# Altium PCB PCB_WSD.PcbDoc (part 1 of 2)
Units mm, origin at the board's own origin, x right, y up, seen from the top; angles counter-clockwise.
Board outline 55.63 x 89.28 mm, 2 copper layers (Top Layer, Bottom Layer); 49 components, 56 nets, 208 pads, 22 vias.
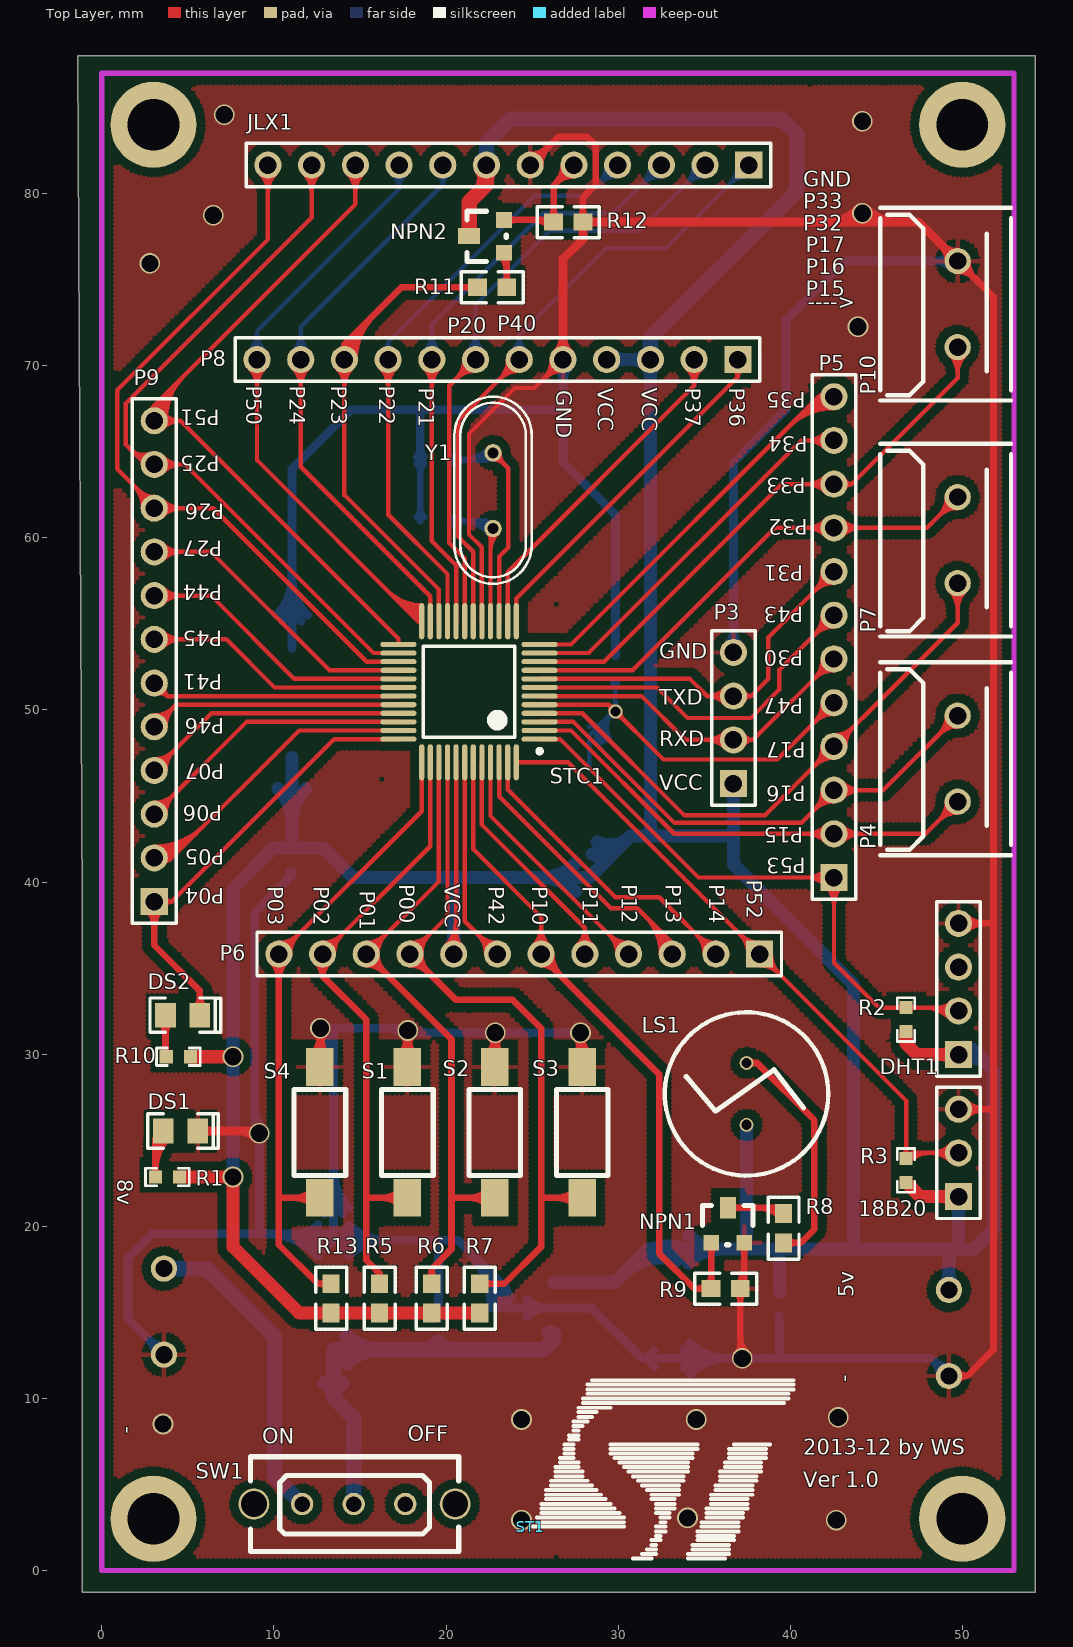
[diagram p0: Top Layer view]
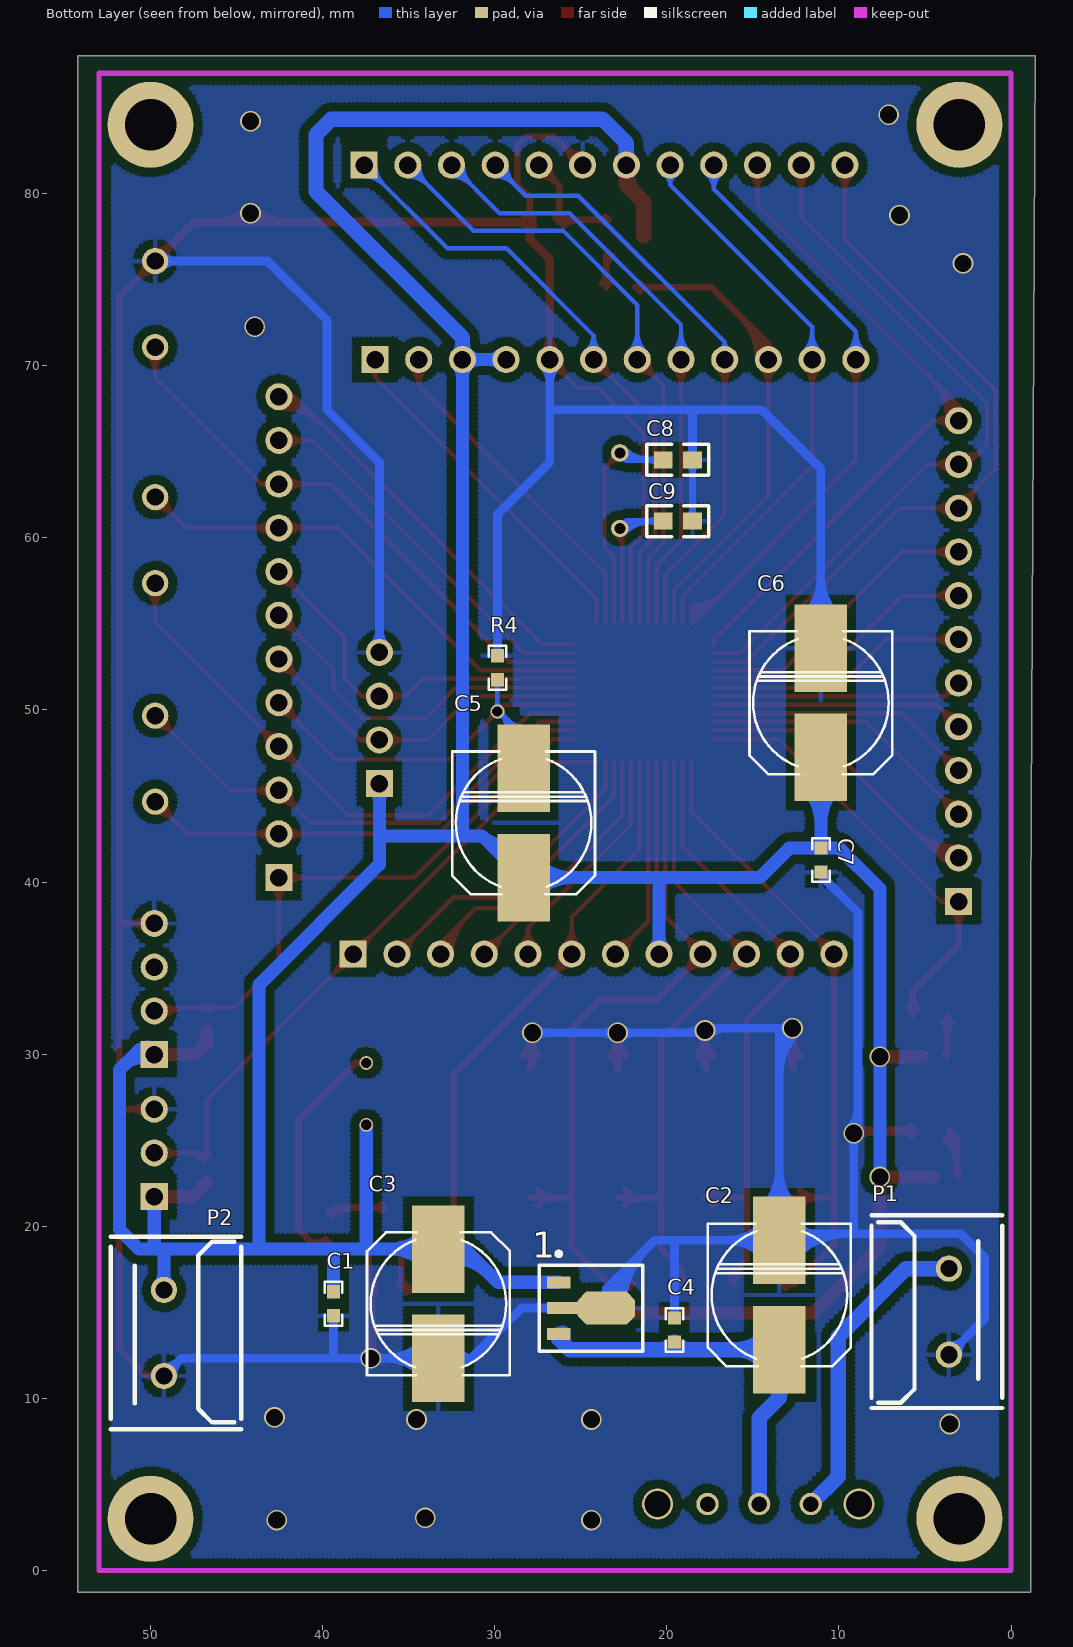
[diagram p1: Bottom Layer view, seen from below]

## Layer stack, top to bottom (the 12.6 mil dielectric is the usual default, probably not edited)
Top Layer: signal copper 0.0356
Dielectric: dielectric 0.32, FR-4, Dk 4.8
Bottom Layer: signal copper 0.0356

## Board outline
-1.397,88.011 54.229,88.011 54.229,-1.27 -1.143,-1.27 -1.143,38.608

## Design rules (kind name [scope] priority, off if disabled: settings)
Clearance Clearance_1 [All vs (INPolygon)] p1: gap=0.508
Clearance [All] p2: gap=0.2
ComponentClearance [All] p1: gap=0.254 collisioncheckmode=2
HoleSize [All] p1: absolutevalues=TRUE maxlimit=5 minlimit=0.025 maxpercent=80.000 minpercent=20.000
PolygonConnect [All] p1: connectstyle=Relief reliefconductorwidth=0.254 reliefentries=4 polygonreliefangle="90 Angle"
RoutingVias [All] p1: holewidth=0.5 width=0.8 viastyle="Through Hole" minholewidth=0.5 minwidth=0.8 maxholewidth=1.2 maxwidth=1.8
SolderMaskExpansion [All] p1: expansion=0.102
TestPointUsage [All] p1: valid=0 allowmultiple=FALSE
Testpoint [All] p1: side=15 testpointundercomponent=TRUE minsize=1.016 maxsize=2.54 preferedsize=1.524 minholesize=0 maxholesize=1.016 preferedholesize=0.813 testpointgrid=0.025 style=1023 order=1234567890
Width [All] p1: maxlimit=1.016 minlimit=0.2 preferedwidth=0.254 toplayer_prefwidth=0.381 bottomlayer_prefwidth=0.508 minimp=50.000000 maximp=50.000000 favimp=50.000000
16 further rules are at their usual default settings.

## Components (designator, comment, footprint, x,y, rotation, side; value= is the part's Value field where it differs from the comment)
1 "78L05-SOT89" SOT89 24.892,15.24 r270 bottom
18B20 "DS18B20" HDR1X3 49.784,21.717 r90 top (schematic designator 2)
C1 "Cap" 0603 39.37,15.494 r90 bottom
C2 "10uf" C310M 13.462,16.002 r270 bottom
C3 "10uf" C310M 33.274,15.494 r90 bottom
C4 "Cap" 0603 19.558,13.97 r270 bottom
C5 "10uf" C310M 28.321,43.434 r270 bottom
C6 "10uf" C310M 11.049,50.419 r270 bottom
C7 "104" 0603 11.049,41.275 r90 bottom
C8 "20pF" P0603 21.209,63.627 r180 bottom
C9 "20pF" P0603 21.209,60.071 r180 bottom
DHT1 "DHT11" HDR1X4 49.784,29.972 r90 top
DS1 "LED0" LED2012 4.572,25.527 r0 top
DS2 "LED0" LED2012 4.699,32.258 r0 top
JLX1 "JLX12864G-086-PC" HDR1X12 37.592,81.661 r180 top
LS1 "Bell" BEEP 37.465,27.686 r90 top
NPN1 "NPN8050" SOT23-T 34.925,18.542 r0 top
NPN2 "NPN8050" SOT23-T 23.876,76.073 r90 top
P1 "MHDR1X2" KF301-2P 0.508,10.033 r90 bottom
P2 "MHDR1X2" KF301-2P 52.324,18.796 r270 bottom
P3 "Header 4" HDR1X4 36.703,45.72 r90 top
P4 "MHDR1X2" KF301-2P 52.832,42.164 r90 top
P5 "Header 12" HDR1X12 42.545,40.259 r90 top
P6 "Header 12" HDR1X12 38.227,35.814 r180 top
P7 "MHDR1X2" KF301-2P 52.832,54.864 r90 top
P8 "Header 12" HDR1X12 36.957,70.358 r180 top
P9 "Header 12" HDR1X12 3.048,38.862 r90 top
P10 "MHDR1X2" KF301-2P 52.832,68.58 r90 top
R1 "Res2" 0603 3.81,22.86 r0 top
R2 "Res2" 0603 46.736,32.004 r270 top
R3 "Res2" 0603 46.736,23.241 r270 top
R4 "10K" 0603 29.845,52.451 r270 bottom
R5 "Res2" P0603 15.24,17.653 r270 top
R6 "Res2" P0603 20.066,13.953 r90 top
R7 "Res2" P0603 22.86,13.953 r90 top
R8 "1K" P0603 40.513,18.034 r90 top
R9 "1K" P0603 38.1,17.272 r180 top
R10 "Res2" 0603 4.445,29.845 r0 top
R11 "10K" P0603 20.828,73.66 r0 top
R12 "1K" P0603 28.956,79.248 r180 top
R13 "Res2" P0603 14.224,13.953 r90 top
S1 "SW-PB" KEY-SMD 16.256,28.448 r270 top
S2 "SW-PB" KEY-SMD 21.336,28.448 r270 top
S3 "SW-PB" KEY-SMD 26.416,28.448 r270 top
S4 "SW-PB" KEY-SMD 11.176,28.448 r270 top
ST1 "ST-WS" ST2 24.892,2.54 r0 top
STC1 "STC12C5A60S2" LQFP48_M 21.336,51.054 r180 top
SW1 "SW-SS12D07" SS-12F44 8.636,6.604 r270 top
Y1 "8MHz" XTA 22.733,62.738 r90 top

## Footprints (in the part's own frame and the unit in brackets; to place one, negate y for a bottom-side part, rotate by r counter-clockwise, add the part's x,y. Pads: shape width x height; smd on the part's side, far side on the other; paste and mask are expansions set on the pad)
0603 [mil]
  rect 30x30 smd: 1(-27.5,0) 2(27.5,0)
  silkscreen extent -50,-20 50,20
BEEP [mm]
  round 0.8 hole 0.6: 1(-1.8,0) 2(1.8,0)
  silkscreen extent -4.75,-4.75 4.75,4.75
C310M [mil]
  rect 200x120 smd: 1(125,0) 2(-125,0)
  silkscreen extent -163,-163 163,163
HDR1X3 [mil] "Connector; Header; 3 Position"
  rect 62x62 hole 40: 1(0,0)
  round 62 hole 40: 2(100,0) 3(200,0)
  silkscreen extent -50,-50 250,50
HDR1X4 [mil] "Connector; Header; 4 Position"
  rect 62x62 hole 40: 1(0,0)
  round 62 hole 40: 2(100,0) 3(200,0) 4(300,0)
  silkscreen extent -50,-50 350,50
HDR1X12 [mil] "Connector; Header; 12 Position"
  rect 62x62 hole 40: 1(0,0)
  round 62 hole 40: 2(100,0) 3(200,0) 4(300,0) 5(400,0) 6(500,0) 7(600,0) 8(700,0) 9(800,0) 10(900,0) 11(1000,0) 12(1100,0)
  silkscreen extent -50,-50 1150,50
KEY-SMD [mm]
  rect 2.2x1.6 smd: 1(-0.8,1.5) 2(6.8,1.5)
  silkscreen extent 0.5,0 5.5,3
KF301-2P [mm]
  round 1.524 hole 1: 1(2.5,3.1) 2(7.5,3.1)
  silkscreen extent -0.6,0 10.6,7.6
LED2012 [mm] "SMD LED 2mm x 1.2 mm"
  rect 1.2x1.45 smd: 1(-1,0) 2(1,0)
  silkscreen extent -1.9,-1 2.2,1
LQFP48_M [mm]
  oval 2.1x0.3 smd: 1(-4.1,2.75) 2(-4.1,2.25) 3(-4.1,1.75) 4(-4.1,1.25) 5(-4.1,0.75) 6(-4.1,0.25) 7(-4.1,-0.25) 8(-4.1,-0.75) 9(-4.1,-1.25) 10(-4.1,-1.75) 11(-4.1,-2.25) 12(-4.1,-2.75) 25(4.1,-2.75) 26(4.1,-2.25) 27(4.1,-1.75) 28(4.1,-1.25) 29(4.1,-0.75) 30(4.1,-0.25) 31(4.1,0.25) 32(4.1,0.75) 33(4.1,1.25) 34(4.1,1.75) 35(4.1,2.25) 36(4.1,2.75)
  oval 0.3x2.1 smd: 13(-2.75,-4.1) 14(-2.25,-4.1) 15(-1.75,-4.1) 16(-1.25,-4.1) 17(-0.75,-4.1) 18(-0.25,-4.1) 19(0.25,-4.1) 20(0.75,-4.1) 21(1.25,-4.1) 22(1.75,-4.1) 23(2.25,-4.1) 24(2.75,-4.1) 37(2.75,4.1) 38(2.25,4.1) 39(1.75,4.1) 40(1.25,4.1) 41(0.75,4.1) 42(0.25,4.1) 43(-0.25,4.1) 44(-0.75,4.1) 45(-1.25,4.1) 46(-1.75,4.1) 47(-2.25,4.1) 48(-2.75,4.1)
  silkscreen extent -4.23,-2.65 2.65,3.57
P0603 [mm]
  rect 1.1x1 smd: 1(1,0.9) 2(2.7,0.9)
  silkscreen extent 0.05,0 3.65,1.8
SOT23-T [mil]
  rect 36x36 smd: 1(19.49,19.69) 2(94.49,19.69)
  rect 36x50 smd: 3(57.49,99.69)
  silkscreen extent -1,15 114,105
SOT89 [mm] "SOT-89; Body 4.6 x 4.25 mm, inc. leads (LxW max)"
  oct 1.9x3.3 smd: 0(0,1.388)
  rect 0.7x1.35 smd: 1(-1.5,-1.388) 3(1.5,-1.388)
  rect 0.7x1.8 smd: 2(0,-1.162)
  silkscreen extent -3.27,-2.51 2.5,3.49
SS-12F44 [mm]
  round 1.8 hole 1.5: 0(2.75,11.9) 0(2.75,0.2)
  round 1.3 hole 0.9: 1(2.75,3) 2(2.75,6) 3(2.75,9)
  silkscreen extent 0,0 5.5,12.1
ST2 [mm]
  silkscreen extent 0.13,-1.85 15.3,8.51
XTA [mil]
  round 40 hole 25: 1(86.61,0) 2(-86.61,0)
  silkscreen extent -213,-89 215,89

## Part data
C1 C4: "Capacitor"
C2 C3 C5 C6: library part "Cap Pol3", "Polarized Capacitor (Surface Mount)"
C7 C8 C9: library part Cap, "Capacitor"
DS1 DS2: "Typical INFRARED GaAs LED"
LS1: "Electrical Bell"
P1 P2 P4 P7 P10: "Header, 2-Pin"
P3: "Header, 4-Pin"
P5 P6 P8 P9: "Header, 12-Pin"
R1 R2 R3 R5 R6 R7 R10 R13: "Resistor"
R4 R8 R9 R11 R12: library part Res2, "Resistor"
S1 S2 S3 S4: "Switch"
Y1: library part XTAL, "Crystal Oscillator"

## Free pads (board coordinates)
  round 5 hole 3: 0(3,3) 0(3,84) 0(50,3) 0(50,84)

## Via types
v1: diameter 1.2, hole 1, Top Layer to Bottom Layer, 21 vias
v2: diameter 0.8, hole 0.6, Top Layer to Bottom Layer, 1 vias

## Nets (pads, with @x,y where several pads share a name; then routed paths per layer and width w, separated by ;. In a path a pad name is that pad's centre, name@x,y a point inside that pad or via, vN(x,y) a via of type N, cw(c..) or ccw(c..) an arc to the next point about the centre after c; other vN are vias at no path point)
5V: 1.1 18B20.1 C1.2 C3.1 C5.1 C6.1 C7.2 DHT1.1 JLX1.7 LS1.1 NPN2.3 P2.1 P3.1 P6.8 P8.3 P8.4 R1.2 R2.2 R3.2 R5.2 R6.1 R7.1 R10.2 R13.1 STC1.41 | length 362.6
  Top Layer w0.254: P6.8@20.447,35.814 20.586,35.953 STC1.41@20.586,46.954 ; P6.8@19.98,36.281 ccw(c18.517,37.744) 20.586,37.744 cw(c18.517,37.744) P6.8@19.98,36.281 ; P6.8@20.16,36.101 ccw(c19.13,37.131) 20.586,37.131 cw(c19.13,37.131) P6.8@20.16,36.101 ; 20.586,37.073 ccw(c21.706,37.073) 20.914,36.281 cw(c21.706,37.073) 20.586,37.073
  Top Layer w0.762: R1.2@4.508,22.86 v1(7.62,22.86) 7.62,18.796 11.463,14.953 R13.1@13.324,14.953 R6.1@19.166,14.953 R7.1@21.96,14.953 ; R10.2@5.143,29.845 v1(7.62,29.845) ; R3.2@46.736,22.543 47.561,21.717 18B20.1@49.784,21.717 ; DHT1.1@49.784,29.972 47.371,29.972 46.736,30.607 R2.2@46.736,31.305 ; R2.2@46.736,31.305 ccw(c47.774,31.073) 47.022,30.321 cw(c47.774,31.073) R2.2@46.736,31.305 ; 48.803,21.717 cw(c48.803,20.736) 49.497,21.43 ccw(c48.803,20.736) 48.803,21.717 ; 48.803,21.717 ccw(c48.803,22.698) 49.497,22.004 cw(c48.803,22.698) 48.803,21.717 ; 48.803,29.972 cw(c48.803,28.991) 49.497,29.685 ccw(c48.803,28.991) 48.803,29.972 ; 48.803,29.972 ccw(c48.803,30.953) 49.497,30.259 cw(c48.803,30.953) 48.803,29.972
  Top Layer w0.889: NPN2.3@21.344,77.533 21.344,79.51 22.352,80.518 JLX1.7@22.352,81.661 ; 22.352,80.833 cw(c23.18,80.833) 22.594,81.419 ccw(c23.18,80.833) 22.352,80.833 ; 22.352,80.833 ccw(c21.524,80.833) 22.11,81.419 cw(c21.524,80.833) 22.352,80.833 ; 21.916,80.082 ccw(c21.127,80.87) 22.064,81.475 cw(c21.127,80.87) 21.916,80.082
  Bottom Layer w0.762: v1(7.62,22.86) 7.62,39.624 9.97,41.974 12.89,41.974 14.605,40.259 C5.1@28.321,40.259 30.734,42.672 ; C7.2@11.049,41.974 C6.1@11.049,47.244 ; P6.8@20.447,35.814 20.447,40.259 ; 1.1@26.28,16.74 29.821,16.74 31.75,18.669 50.673,18.669 51.816,19.812 51.816,29.083 50.927,29.972 DHT1.1@49.784,29.972 ; P8.4@29.337,70.358 P8.3@31.877,70.358 31.877,42.672 ; 36.703,42.672 30.734,42.672 ; P3.1@36.703,45.72 36.703,41.021 43.688,34.036 43.688,18.669 ; 37.465,18.669 LS1.1@37.465,25.886 ; C1.2@39.37,16.192 39.37,18.669 ; P2.1@49.121,16.192 P2.1@49.224,16.296 49.224,18.594 49.149,18.669 ; 49.784,18.669 18B20.1@49.784,21.717 ; 11.049,43.469 cw(c13.808,43.469) 11.857,45.42 ccw(c13.808,43.469) 11.049,43.469 ; 11.049,43.469 ccw(c8.29,43.469) 10.241,45.42 cw(c8.29,43.469) 11.049,43.469 ; 20.447,36.795 cw(c19.466,36.795) 20.16,36.101 ccw(c19.466,36.795) 20.447,36.795 ; 20.447,36.795 ccw(c21.428,36.795) 20.734,36.101 cw(c21.428,36.795) 20.447,36.795 ; 25.562,40.259 cw(c25.562,37.5) 27.513,39.451 ccw(c25.562,37.5) 25.562,40.259 ; 25.562,40.259 ccw(c25.562,43.018) 27.513,41.067 cw(c25.562,43.018) 25.562,40.259 ; 30.318,70.358 cw(c30.318,71.339) 29.624,70.645 ccw(c30.318,71.339) 30.318,70.358 ; 30.318,70.358 ccw(c30.318,69.377) 29.624,70.071 cw(c30.318,69.377) 30.318,70.358 ; 30.734,42.672 cw(c29.506,43.9) 28.791,42.317 ccw(c29.506,43.9) 30.734,42.672 ; 30.896,70.358 cw(c30.896,69.377) P8.3@31.59,70.071 ; 30.896,70.358 ccw(c30.896,71.339) 31.59,70.645 cw(c30.896,71.339) 30.896,70.358 ; 30.896,70.358 cw(c30.896,69.377) P8.3@31.59,70.071 ; P8.3@31.59,70.071 cw(c30.896,69.377) 31.877,69.377 ; P8.3@31.59,70.071 cw(c30.896,69.377) 31.877,69.377 ; 31.877,69.377 cw(c32.858,69.377) 32.164,70.071 ccw(c32.858,69.377) 31.877,69.377 ; 36.033,18.669 cw(c36.033,21.428) 34.082,19.477 ccw(c36.033,21.428) 36.033,18.669 ; 36.033,18.669 ccw(c36.033,15.91) 34.082,17.861 cw(c36.033,15.91) 36.033,18.669 ; 36.703,44.739 cw(c37.684,44.739) 36.99,45.433 ccw(c37.684,44.739) 36.703,44.739 ; 36.703,44.739 ccw(c35.722,44.739) 36.416,45.433 cw(c35.722,44.739) 36.703,44.739 ; 49.224,17.216 cw(c48.304,17.216) 48.955,16.565 ccw(c48.304,17.216) 49.224,17.216 ; 49.224,17.216 ccw(c50.144,17.216) 49.493,16.565 cw(c50.144,17.216) 49.224,17.216 ; 49.784,20.736 cw(c50.765,20.736) 50.071,21.43 ccw(c50.765,20.736) 49.784,20.736 ; 49.784,20.736 ccw(c48.803,20.736) 49.497,21.43 cw(c48.803,20.736) 49.784,20.736 ; 50.765,29.972 cw(c50.765,30.953) 50.071,30.259 ccw(c50.765,30.953) 50.765,29.972 ; 50.765,29.972 ccw(c50.765,28.991) 50.071,29.685 cw(c50.765,28.991) 50.765,29.972 ; C5.1@28.478,41.622 ccw(c29.021,42.826) 29.954,41.892 cw(c29.021,42.826) C5.1@28.478,41.622 ; 30.342,17.261 cw(c32.492,15.11) 33.386,18.017 ccw(c32.492,15.11) 30.342,17.261 ; 31.237,18.156 cw(c32.913,16.479) 33.61,18.746 ccw(c32.913,16.479) 31.237,18.156 ; DHT1.1@49.612,30.283 cw(c50.087,29.423) 50.781,30.118 ccw(c50.087,29.423) DHT1.1@49.612,30.283 ; DHT1.1@49.779,30.328 cw(c49.806,28.479) 51.113,29.786 ccw(c49.806,28.479) DHT1.1@49.779,30.328 ; DHT1.1@49.98,29.616 cw(c50.596,28.498) 51.498,29.401 ccw(c50.596,28.498) DHT1.1@49.98,29.616
  Bottom Layer w0.889: JLX1.7@22.352,81.661 22.352,82.931 23.749,84.328 39.497,84.328 40.386,83.439 40.386,80.137 31.877,71.628 P8.3@31.877,70.358 ; 22.352,82.489 cw(c21.524,82.489) 22.11,81.903 ccw(c21.524,82.489) 22.352,82.489 ; 22.352,82.489 ccw(c23.18,82.489) 22.594,81.903 cw(c23.18,82.489) 22.352,82.489 ; 31.877,71.186 cw(c31.049,71.186) 31.635,70.6 ccw(c31.049,71.186) 31.877,71.186 ; 31.877,71.186 ccw(c32.705,71.186) 32.119,70.6 cw(c32.705,71.186) 31.877,71.186
8V: P1.2 SW1.1 | length 20.9
  Bottom Layer w0.889: P1.2@3.608,17.533 6.089,17.533 10.033,13.589 10.033,5.457 SW1.1@11.636,3.854 ; 4.375,17.533 cw(c4.375,18.3) 3.833,17.758 ccw(c4.375,18.3) 4.375,17.533 ; 4.375,17.533 ccw(c4.375,16.766) 3.833,17.308 cw(c4.375,16.766) 4.375,17.533
18B20: 18B20.2 P6.1 R3.1 STC1.48 | length 67.9
  Top Layer w0.254: STC1.48@24.086,46.954 27.087,46.954 46.736,27.305 R3.1@46.736,23.939 ; 18B20.2@49.784,24.257 47.053,24.257 R3.1@46.736,23.939 ; 37.1,36.941 cw(c35.972,35.814) 37.567,35.814 ccw(c35.972,35.814) 37.1,36.941 ; 37.1,36.941 ccw(c38.227,38.069) 38.227,36.474 cw(c38.227,38.069) 37.1,36.941 ; P6.1@37.533,36.508 cw(c36.839,35.814) 37.821,35.814 ccw(c36.839,35.814) P6.1@37.533,36.508 ; P6.1@37.533,36.508 ccw(c38.227,37.202) 38.227,36.22 cw(c38.227,37.202) P6.1@37.533,36.508 ; P6.1@38.921,35.12 cw(c39.615,35.814) 38.633,35.814 ccw(c39.615,35.814) P6.1@38.921,35.12 ; P6.1@38.921,35.12 ccw(c38.227,34.426) 38.227,35.408 cw(c38.227,34.426) P6.1@38.921,35.12 ; 39.354,34.687 cw(c40.482,35.814) 38.887,35.814 ccw(c40.482,35.814) 39.354,34.687 ; 39.354,34.687 ccw(c38.227,33.559) 38.227,35.154 cw(c38.227,33.559) 39.354,34.687 ; R3.1@46.736,23.939 cw(c47.503,23.173) 47.503,24.257 ccw(c47.503,23.173) R3.1@46.736,23.939 ; 46.736,24.553 cw(c46.123,24.553) 46.556,24.119 ccw(c46.123,24.553) 46.736,24.553 ; 46.736,24.553 ccw(c47.349,24.553) 46.916,24.119 cw(c47.349,24.553) 46.736,24.553 ; 48.19,24.257 cw(c48.19,22.663) 49.317,23.79 ccw(c48.19,22.663) 48.19,24.257 ; 48.19,24.257 ccw(c48.19,25.851) 49.317,24.724 cw(c48.19,25.851) 48.19,24.257 ; 48.803,24.257 cw(c48.803,23.276) 49.497,23.97 ccw(c48.803,23.276) 48.803,24.257 ; 48.803,24.257 ccw(c48.803,25.238) 49.497,24.544 cw(c48.803,25.238) 48.803,24.257 ; R3.1@46.916,23.76 cw(c48.116,22.56) 48.116,24.257 ccw(c48.116,22.56) R3.1@46.916,23.76
BEEP: NPN1.1 P6.6 R9.2 STC1.43 | length 58.9
  Top Layer w0.254: STC1.43@21.586,46.954 21.586,41.914 25.527,37.973 P6.6@25.527,35.814 ; 25.527,36.795 cw(c24.546,36.795) 25.24,36.101 ccw(c24.546,36.795) 25.527,36.795 ; 25.527,36.795 ccw(c26.508,36.795) 25.814,36.101 cw(c26.508,36.795) 25.527,36.795 ; 25.527,37.408 cw(c23.933,37.408) 25.06,36.281 ccw(c23.933,37.408) 25.527,37.408 ; 25.527,37.408 ccw(c27.121,37.408) 25.994,36.281 cw(c27.121,37.408) 25.527,37.408
  Top Layer w0.381: P6.6@25.527,35.814 25.527,35.687 32.385,28.829 32.385,18.415 34.428,16.372 R9.2@35.4,16.372 35.42,16.392 NPN1.1@35.42,19.042 ; 34.603,16.372 cw(c34.603,15.625) 35.131,16.153 ccw(c34.603,15.625) 34.603,16.372 ; 34.603,16.372 ccw(c34.603,17.119) 35.131,16.591 cw(c34.603,17.119) 34.603,16.372 ; 35.42,18.398 cw(c36.064,18.398) 35.609,18.853 ccw(c36.064,18.398) 35.42,18.398 ; 35.42,18.398 ccw(c34.776,18.398) 35.231,18.853 cw(c34.776,18.398) 35.42,18.398 ; P6.6@25.527,35.217 cw(c25.527,34.083) 26.329,34.885 ccw(c25.527,34.083) P6.6@25.527,35.217 ; P6.6@26.124,35.814 ccw(c27.872,35.814) 26.636,34.578 cw(c27.872,35.814) P6.6@26.124,35.814 ; R9.2@35.181,16.591 ccw(c34.605,17.167) 35.42,17.167 cw(c34.605,17.167) R9.2@35.181,16.591 ; 35.42,17.071 ccw(c36.099,17.071) 35.619,16.591 cw(c36.099,17.071) 35.42,17.071
DHT: DHT1.2 P5.1 R2.1 STC1.1 | length 63
  Top Layer w0.254: STC1.1@25.436,48.304 26.626,48.304 34.671,40.259 P5.1@42.545,40.259 42.545,35.306 45.148,32.703 R2.1@46.736,32.703 49.593,32.703 DHT1.2@49.784,32.512 ; 40.951,40.259 cw(c40.951,38.665) P5.1@42.078,39.792 ; 40.951,40.259 ccw(c40.951,41.853) 42.078,40.726 cw(c40.951,41.853) 40.951,40.259 ; 40.951,40.259 cw(c40.951,38.665) P5.1@42.078,39.792 ; 41.564,40.259 cw(c41.564,39.278) P5.1@42.258,39.972 ; 41.564,40.259 ccw(c41.564,41.24) 42.258,40.546 cw(c41.564,41.24) 41.564,40.259 ; 41.564,40.259 cw(c41.564,39.278) P5.1@42.258,39.972 ; P5.1@42.078,39.792 cw(c40.951,38.665) 42.545,38.665 ; P5.1@42.078,39.792 cw(c40.951,38.665) 42.545,38.665 ; P5.1@42.258,39.972 cw(c41.564,39.278) 42.545,39.278 ; P5.1@42.258,39.972 cw(c41.564,39.278) 42.545,39.278 ; 42.545,38.665 cw(c44.139,38.665) 43.012,39.792 ccw(c44.139,38.665) 42.545,38.665 ; 42.545,39.278 cw(c43.526,39.278) 42.832,39.972 ccw(c43.526,39.278) 42.545,39.278 ; 46.123,32.703 cw(c46.123,32.089) 46.556,32.523 ccw(c46.123,32.089) 46.123,32.703 ; 46.123,32.703 ccw(c46.123,33.316) 46.556,32.882 cw(c46.123,33.316) 46.123,32.703 ; 47.349,32.703 cw(c47.349,33.316) 46.916,32.882 ccw(c47.349,33.316) 47.349,32.703 ; 47.349,32.703 ccw(c47.349,32.089) 46.916,32.523 cw(c47.349,32.089) 47.349,32.703 ; 47.73,32.703 cw(c47.73,30.458) 49.317,32.045 ccw(c47.73,30.458) 47.73,32.703 ; 48.343,32.703 cw(c48.343,31.071) 49.497,32.225 ccw(c48.343,31.071) 48.343,32.703 ; 48.65,32.703 ccw(c48.65,33.646) 49.317,32.979 cw(c48.65,33.646) 48.65,32.703 ; 48.956,32.703 cw(c48.956,31.684) 49.676,32.404 ccw(c48.956,31.684) 48.956,32.703
DS-IO: P9.8 STC1.29 | length 24.3
  Top Layer w0.254: P9.8@3.048,56.642 6.35,56.642 11.188,51.804 STC1.29@17.236,51.804 ; 4.029,56.642 cw(c4.029,57.623) 3.335,56.929 ccw(c4.029,57.623) 4.029,56.642 ; 4.029,56.642 ccw(c4.029,55.661) 3.335,56.355 cw(c4.029,55.661) 4.029,56.642 ; 4.642,56.642 cw(c4.642,58.236) 3.515,57.109 ccw(c4.642,58.236) 4.642,56.642 ; 4.642,56.642 ccw(c4.642,55.048) 3.515,56.175 cw(c4.642,55.048) 4.642,56.642
DS-R\S\T\: P9.9 STC1.28 | length 25.1
  Top Layer w0.254: P9.9@3.048,59.182 6.35,59.182 13.228,52.304 STC1.28@17.236,52.304 ; 4.029,59.182 cw(c4.029,60.163) 3.335,59.469 ccw(c4.029,60.163) 4.029,59.182 ; 4.029,59.182 ccw(c4.029,58.201) 3.335,58.895 cw(c4.029,58.201) 4.029,59.182 ; 4.642,59.182 cw(c4.642,60.776) 3.515,59.649 ccw(c4.642,60.776) 4.642,59.182 ; 4.642,59.182 ccw(c4.642,57.588) 3.515,58.715 cw(c4.642,57.588) 4.642,59.182
DS-SCK: P9.7 STC1.30 | length 23.4
  Top Layer w0.254: P9.7@3.048,54.102 7.239,54.102 10.037,51.304 STC1.30@17.236,51.304 ; 4.029,54.102 cw(c4.029,55.083) 3.335,54.389 ccw(c4.029,55.083) 4.029,54.102 ; 4.029,54.102 ccw(c4.029,53.121) 3.335,53.815 cw(c4.029,53.121) 4.029,54.102 ; 4.642,54.102 cw(c4.642,55.696) 3.515,54.569 ccw(c4.642,55.696) 4.642,54.102 ; 4.642,54.102 ccw(c4.642,52.508) 3.515,53.635 cw(c4.642,52.508) 4.642,54.102
GND: 1.0 1.2 18B20.3 C1.1 C2.2 C3.2 C4.1 C6.2 C7.1 C8.2 C9.2 DHT1.4 DS1.2 JLX1.6 NPN1.2 P1.1 P2.2 P3.4 P8.5 P10.2 R4.1 R9.1 R12.1 S1.1 S2.1 S3.1 S4.1 STC1.17 | length 615.3
  Top Layer w0.254: STC1.17@22.086,55.154 22.086,59.448 21.336,60.198 21.336,66.04 24.003,68.707 25.146,68.707 P8.5@26.797,70.358 ; 25.67,69.231 cw(c26.797,68.103) 26.797,69.698 ccw(c26.797,68.103) 25.67,69.231 ; 25.67,69.231 ccw(c24.542,70.358) 26.137,70.358 cw(c24.542,70.358) 25.67,69.231 ; 26.103,69.664 cw(c26.797,68.97) 26.797,69.952 ccw(c26.797,68.97) 26.103,69.664 ; 26.103,69.664 ccw(c25.409,70.358) 26.391,70.358 cw(c25.409,70.358) 26.103,69.664
  Top Layer w0.381: JLX1.6@24.892,81.661 26.543,83.312 28.194,83.312 28.702,82.804 28.702,80.518 27.956,79.772 R12.1@27.956,78.348 ; v1(37.211,12.319) 37.1,12.43 R9.1@37.1,16.372 37.325,16.597 NPN1.2@37.325,19.042 ; P2.2@49.224,11.296 50.285,11.296 ; P10.2@49.732,76.08 51.816,73.996 51.816,12.827 50.285,11.296 ; 18B20.3@49.784,26.797 51.816,26.797 ; DHT1.4@49.784,37.592 51.816,37.592 ; 25.911,82.68 cw(c24.892,83.699) 24.892,82.258 ccw(c24.892,83.699) 25.911,82.68 ; 25.911,82.68 ccw(c26.93,81.661) 25.489,81.661 cw(c26.93,81.661) 25.911,82.68 ; 27.956,79.095 cw(c27.209,79.095) 27.737,78.567 ccw(c27.209,79.095) 27.956,79.095 ; 27.956,79.095 ccw(c28.703,79.095) 28.175,78.567 cw(c28.703,79.095) 27.956,79.095 ; 37.1,15.625 cw(c37.847,15.625) 37.319,16.153 ccw(c37.847,15.625) 37.1,15.625 ; 37.1,15.625 ccw(c36.353,15.625) 36.881,16.153 cw(c36.353,15.625) 37.1,15.625 ; 37.325,18.398 cw(c37.969,18.398) 37.514,18.853 ccw(c37.969,18.398) 37.325,18.398 ; 37.325,18.398 ccw(c36.681,18.398) 37.136,18.853 cw(c36.681,18.398) 37.325,18.398 ; 50.285,11.296 cw(c50.285,11.995) 49.701,11.61 ccw(c50.285,11.995) 50.285,11.296 ; 50.285,11.296 ccw(c50.285,10.597) 49.701,10.982 cw(c50.285,10.597) 50.285,11.296 ; 50.708,75.104 cw(c51.683,76.08) 50.304,76.08 ccw(c51.683,76.08) 50.708,75.104 ; 50.708,75.104 ccw(c49.732,74.129) 49.732,75.509 cw(c49.732,74.129) 50.708,75.104 ; 51.225,26.797 cw(c51.225,28.238) 50.206,27.219 ccw(c51.225,28.238) 51.225,26.797 ; 51.225,26.797 ccw(c51.225,25.356) 50.206,26.375 cw(c51.225,25.356) 51.225,26.797 ; 51.225,37.592 cw(c51.225,39.033) 50.206,38.014 ccw(c51.225,39.033) 51.225,37.592 ; 51.225,37.592 ccw(c51.225,36.151) 50.206,37.17 cw(c51.225,36.151) 51.225,37.592 ; v1@36.921,12.609 ccw(c36.49,13.04) 37.1,13.04 cw(c36.49,13.04) v1@36.921,12.609 ; R9.1@36.931,16.591 ccw(c35.98,17.542) 37.325,17.542 cw(c35.98,17.542) R9.1@36.931,16.591 ; 37.1,13.576 ccw(c38.468,13.576) 37.501,12.609 cw(c38.468,13.576) 37.1,13.576
  Top Layer w0.508: DS1.2@5.572,25.527 9.017,25.527 v1(9.144,25.4) ; S4.1@12.676,29.248 12.7,29.272 v1(12.7,31.496) ; S1.1@17.756,29.248 17.78,29.272 v1(17.78,31.369) ; S2.1@22.836,29.248 22.86,29.272 v1(22.86,31.242) ; P8.5@26.797,70.358 26.797,76.2 27.956,77.359 R12.1@27.956,78.348 47.464,78.348 P10.2@49.732,76.08 ; v1(27.813,31.242) 27.813,29.351 S3.1@27.916,29.248 ; 6.407,25.527 cw(c6.407,26.362) 5.817,25.772 ccw(c6.407,26.362) 6.407,25.527 ; 6.407,25.527 ccw(c6.407,24.692) 5.817,25.282 cw(c6.407,24.692) 6.407,25.527 ; 12.7,30.661 cw(c13.535,30.661) 12.945,31.251 ccw(c13.535,30.661) 12.7,30.661 ; 12.7,30.661 ccw(c11.865,30.661) 12.455,31.251 cw(c11.865,30.661) 12.7,30.661 ; 17.78,30.534 cw(c18.615,30.534) 18.025,31.124 ccw(c18.615,30.534) 17.78,30.534 ; 17.78,30.534 ccw(c16.945,30.534) 17.535,31.124 cw(c16.945,30.534) 17.78,30.534 ; 22.86,30.407 cw(c23.695,30.407) 23.105,30.997 ccw(c23.695,30.407) 22.86,30.407 ; 22.86,30.407 ccw(c22.025,30.407) 22.615,30.997 cw(c22.025,30.407) 22.86,30.407 ; 26.797,71.646 cw(c25.509,71.646) 26.42,70.735 ccw(c25.509,71.646) 26.797,71.646 ; 26.797,71.646 ccw(c28.085,71.646) 27.174,70.735 cw(c28.085,71.646) 26.797,71.646 ; 27.813,30.407 cw(c28.648,30.407) 28.058,30.997 ccw(c28.648,30.407) 27.813,30.407 ; 27.813,30.407 ccw(c26.978,30.407) 27.568,30.997 cw(c26.978,30.407) 27.813,30.407 ; 27.956,77.754 cw(c28.55,77.754) 28.13,78.174 ccw(c28.55,77.754) 27.956,77.754 ; 27.956,77.754 ccw(c27.362,77.754) 27.782,78.174 cw(c27.362,77.754) 27.956,77.754 ; 28.6,78.348 cw(c28.6,78.942) 28.18,78.522 ccw(c28.6,78.942) 28.6,78.348 ; 28.6,78.348 ccw(c28.6,77.754) 28.18,78.174 cw(c28.6,77.754) 28.6,78.348 ; 48.865,76.947 cw(c47.998,76.08) 49.224,76.08 ccw(c47.998,76.08) 48.865,76.947 ; 48.865,76.947 ccw(c49.732,77.814) 49.732,76.588 cw(c49.732,77.814) 48.865,76.947 ; 8.002,25.527 cw(c8.002,24.258) 8.899,25.155 ccw(c8.002,24.258) 8.002,25.527 ; S4.1@12.29,29.934 ccw(c11.3,30.924) 12.7,30.924 cw(c11.3,30.924) S4.1@12.29,29.934 ; 12.7,30.808 ccw(c13.936,30.808) 13.062,29.934 cw(c13.936,30.808) 12.7,30.808 ; S1.1@17.37,29.934 ccw(c16.38,30.924) 17.78,30.924 cw(c16.38,30.924) S1.1@17.37,29.934 ; v1@17.78,30.808 ccw(c19.016,30.808) 18.142,29.934 cw(c19.016,30.808) v1@17.78,30.808 ; S2.1@22.45,29.934 ccw(c21.46,30.924) 22.86,30.924 cw(c21.46,30.924) S2.1@22.45,29.934 ; v1@22.86,30.808 ccw(c24.096,30.808) 23.222,29.934 cw(c24.096,30.808) v1@22.86,30.808 ; S3.1@27.53,29.934 ccw(c26.847,30.617) 27.813,30.617 cw(c26.847,30.617) S3.1@27.53,29.934 ; v1@27.813,31.115 ccw(c29.483,31.115) 28.302,29.934 cw(c29.483,31.115) v1@27.813,31.115 ; 42.108,78.348 ccw(c42.108,80.955) 43.951,79.112 cw(c42.108,80.955) 42.108,78.348 ; 43.334,78.348 ccw(c43.334,79.729) 44.311,78.752 cw(c43.334,79.729) 43.334,78.348 ; v1@44.081,78.752 ccw(c45.058,79.729) 45.058,78.348 cw(c45.058,79.729) v1@44.081,78.752 ; v1@44.441,79.112 ccw(c46.284,80.955) 46.284,78.348 cw(c46.284,80.955) v1@44.441,79.112
  Bottom Layer w0.381: C9.2@18.509,60.971 C8.2@18.509,64.527 ; 18.509,61.718 cw(c17.762,61.718) 18.29,61.19 ccw(c17.762,61.718) 18.509,61.718 ; 18.509,61.718 ccw(c19.256,61.718) 18.728,61.19 cw(c19.256,61.718) 18.509,61.718 ; 18.509,63.78 cw(c19.256,63.78) 18.728,64.308 ccw(c19.256,63.78) 18.509,63.78 ; 18.509,63.78 ccw(c17.762,63.78) 18.29,64.308 cw(c17.762,63.78) 18.509,63.78
  Bottom Layer w0.508: P1.1@3.608,12.533 1.524,14.617 1.524,18.161 2.921,19.558 13.081,19.558 C2.2@13.462,19.177 ; 9.144,19.558 v1(9.144,25.4) 8.89,25.654 8.89,38.227 11.049,40.386 C7.1@11.049,40.576 ; C6.2@11.049,53.594 11.049,64.008 14.478,67.437 26.797,67.437 ; v1(12.7,31.496) 17.653,31.496 17.907,31.242 v1(27.813,31.242) ; 13.589,31.496 13.462,31.369 C2.2@13.462,19.177 ; C8.2@18.509,64.527 18.509,67.277 18.669,67.437 ; C4.1@19.558,14.668 19.558,19.177 ; P8.5@26.797,70.358 26.797,64.389 29.845,61.341 R4.1@29.845,53.149 ; P3.4@36.703,53.34 36.703,64.389 39.751,67.437 39.751,72.644 43.187,76.08 P10.2@49.732,76.08 ; 39.37,12.319 C1.1@39.37,14.795 ; P2.2@49.224,11.296 48.201,12.319 31.369,12.319 ; 2.741,13.4 cw(c1.874,12.533) 3.1,12.533 ccw(c1.874,12.533) 2.741,13.4 ; 2.741,13.4 ccw(c3.608,14.267) 3.608,13.041 cw(c3.608,14.267) 2.741,13.4 ; 9.144,24.565 cw(c9.979,24.565) 9.389,25.155 ccw(c9.979,24.565) 9.144,24.565 ; 9.144,24.565 ccw(c8.309,24.565) 8.899,25.155 cw(c8.309,24.565) 9.144,24.565 ; 11.049,56.45 cw(c9.209,56.45) 10.51,55.149 ccw(c9.209,56.45) 11.049,56.45 ; 11.049,56.45 ccw(c12.889,56.45) 11.588,55.149 cw(c12.889,56.45) 11.049,56.45 ; 11.049,57.676 cw(c7.983,57.676) 10.151,55.508 ccw(c7.983,57.676) 11.049,57.676 ; 11.049,57.676 ccw(c14.115,57.676) 11.947,55.508 cw(c14.115,57.676) 11.049,57.676 ; C2.2@13.462,19.177 20.701,19.177 23.504,16.374 1.0@23.504,15.24 1.2@26.054,15.24 28.448,15.24 31.369,12.319 ; 13.462,22.033 cw(c11.622,22.033) 12.923,20.732 ccw(c11.622,22.033) 13.462,22.033 ; 13.462,22.033 ccw(c15.302,22.033) 14.001,20.732 cw(c15.302,22.033) 13.462,22.033 ; 13.462,23.259 cw(c10.396,23.259) 12.564,21.091 ccw(c10.396,23.259) 13.462,23.259 ; 13.462,23.259 ccw(c16.528,23.259) 14.36,21.091 cw(c16.528,23.259) 13.462,23.259 ; 13.535,31.496 cw(c13.535,32.331) 12.945,31.741 ccw(c13.535,32.331) 13.535,31.496 ; 13.535,31.496 ccw(c13.535,30.661) 12.945,31.251 cw(c13.535,30.661) 13.535,31.496 ; 15.302,19.177 cw(c15.302,21.017) 14.001,19.716 ccw(c15.302,21.017) 15.302,19.177 ; 15.302,19.177 ccw(c15.302,17.337) 14.001,18.638 cw(c15.302,17.337) 15.302,19.177 ; 16.528,19.177 cw(c16.528,22.243) 14.36,20.075 ccw(c16.528,22.243) 16.528,19.177 ; 16.528,19.177 ccw(c16.528,16.111) 14.36,18.279 cw(c16.528,16.111) 16.528,19.177 ; 18.509,65.121 cw(c17.915,65.121) 18.335,64.701 ccw(c17.915,65.121) 18.509,65.121 ; 18.509,65.121 ccw(c19.103,65.121) 18.683,64.701 cw(c19.103,65.121) 18.509,65.121 ; 22.025,31.242 cw(c22.025,30.407) 22.615,30.997 ccw(c22.025,30.407) 22.025,31.242 ; 22.025,31.242 ccw(c22.025,32.077) 22.615,31.487 cw(c22.025,32.077) 22.025,31.242 ; 23.504,16.373 cw(c22.929,16.373) 23.19,15.861 ccw(c22.929,16.373) 23.504,16.373 ; 23.504,16.373 ccw(c24.08,16.373) 23.819,15.861 cw(c24.08,16.373) 23.504,16.373 ; 23.695,31.242 cw(c23.695,32.077) 23.105,31.487 ccw(c23.695,32.077) 23.695,31.242 ; 23.695,31.242 ccw(c23.695,30.407) 23.105,30.997 cw(c23.695,30.407) 23.695,31.242 ; 1.2@25.885,15.24 cw(c25.885,16.92) 24.697,15.732 ccw(c25.885,16.92) 1.2@25.885,15.24 ; 1.2@25.885,15.24 ccw(c25.885,13.56) 24.697,14.748 cw(c25.885,13.56) 1.2@25.885,15.24 ; 26.797,69.07 cw(c28.085,69.07) 27.174,69.981 ccw(c28.085,69.07) 26.797,69.07 ; 26.797,69.07 ccw(c25.509,69.07) 26.42,69.981 cw(c25.509,69.07) 26.797,69.07 ; 26.978,31.242 cw(c26.978,30.407) 27.568,30.997 ccw(c26.978,30.407) 26.978,31.242 ; 26.978,31.242 ccw(c26.978,32.077) 27.568,31.487 cw(c26.978,32.077) 26.978,31.242 ; 31.369,12.319 cw(c31.369,11.525) 32.102,11.831 ccw(c31.369,11.525) 31.369,12.319 ; 31.369,12.319 ccw(c31.369,13.113) 32.102,12.807 cw(c31.369,13.113) 31.369,12.319 ; 35.114,12.319 cw(c35.114,14.159) 33.813,12.858 ccw(c35.114,14.159) 35.114,12.319 ; 35.114,12.319 ccw(c35.114,10.479) 33.813,11.78 cw(c35.114,10.479) 35.114,12.319 ; 36.34,12.319 cw(c36.34,15.385) 34.172,13.217 ccw(c36.34,15.385) 36.34,12.319 ; 36.34,12.319 ccw(c36.34,9.253) 34.172,11.421 cw(c36.34,9.253) 36.34,12.319 ; 36.376,12.319 cw(c36.376,11.484) 36.966,12.074 ccw(c36.376,11.484) 36.376,12.319 ; 36.376,12.319 ccw(c36.376,13.154) 36.966,12.564 cw(c36.376,13.154) 36.376,12.319 ; 36.703,54.628 cw(c35.415,54.628) 36.326,53.717 ccw(c35.415,54.628) 36.703,54.628 ; 36.703,54.628 ccw(c37.991,54.628) 37.08,53.717 cw(c37.991,54.628) 36.703,54.628 ; 38.046,12.319 cw(c38.046,13.154) 37.456,12.564 ccw(c38.046,13.154) 38.046,12.319 ; 38.046,12.319 ccw(c38.046,11.484) 37.456,12.074 cw(c38.046,11.484) 38.046,12.319 ; 48.357,12.163 cw(c47.49,11.296) 48.716,11.296 ccw(c47.49,11.296) 48.357,12.163 ; 48.357,12.163 ccw(c49.224,13.03) 49.224,11.804 cw(c49.224,13.03) 48.357,12.163 ; 48.506,76.08 cw(c48.506,74.854) 49.373,75.721 ccw(c48.506,74.854) 48.506,76.08 ; 48.506,76.08 ccw(c48.506,77.306) 49.373,76.439 cw(c48.506,77.306) 48.506,76.08 ; 8.89,26.849 ccw(c10.593,26.849) 9.389,25.645 cw(c10.593,26.849) 8.89,26.849 ; 9.476,19.558 cw(c9.476,15.191) 12.564,18.279 ccw(c9.476,15.191) 9.476,19.558 ; 10.697,40.034 ccw(c10.155,40.576) 10.922,40.576 cw(c10.155,40.576) 10.697,40.034 ; 10.703,19.558 cw(c10.703,16.418) 12.923,18.638 ccw(c10.703,16.418) 10.703,19.558 ; 11.316,19.558 ccw(c11.316,21.323) 12.564,20.075 cw(c11.316,21.323) 11.316,19.558 ; 11.929,19.558 cw(c11.929,17.644) 13.282,18.997 ccw(c11.929,17.644) 11.929,19.558 ; v1@12.455,31.251 cw(c10.025,28.821) 13.462,28.821 ccw(c10.025,28.821) v1@12.455,31.251 ; v1@12.815,31.611 cw(c11.251,30.047) 13.462,30.047 ccw(c11.251,30.047) v1@12.815,31.611 ; 16.638,31.496 cw(c16.638,30.227) 17.535,31.124 ccw(c16.638,30.227) 16.638,31.496 ; v1@18.025,31.614 ccw(c18.922,32.511) 18.922,31.242 cw(c18.922,32.511) v1@18.025,31.614 ; 21.187,18.691 cw(c17.736,15.24) 22.617,15.24 ccw(c17.736,15.24) 21.187,18.691 ; 22.054,17.824 cw(c19.471,15.24) 23.125,15.24 ccw(c19.471,15.24) 22.054,17.824 ; 22.922,16.956 cw(c21.205,15.24) 23.633,15.24 ccw(c21.205,15.24) 22.922,16.956
  other v1: 24.384,2.921 42.672,2.921 34.036,3.048 3.556,8.509 24.384,8.763 34.544,8.763 42.799,8.89 43.942,72.263 2.794,75.946 6.477,78.74 44.196,78.867 44.196,84.201 7.112,84.582
KEY-C: P6.12 R13.2 S4.2 STC1.37 | length 57.4
  Top Layer w0.254: P6.12@10.287,35.814 18.586,44.113 STC1.37@18.586,46.954 ; 10.981,36.508 cw(c10.287,37.202) 10.287,36.22 ccw(c10.287,37.202) 10.981,36.508 ; 10.981,36.508 ccw(c11.675,35.814) 10.693,35.814 cw(c11.675,35.814) 10.981,36.508 ; 11.414,36.941 cw(c10.287,38.069) 10.287,36.474 ccw(c10.287,38.069) 11.414,36.941 ; 11.414,36.941 ccw(c12.542,35.814) 10.947,35.814 cw(c12.542,35.814) 11.414,36.941
  Top Layer w0.381: P6.12@10.287,35.814 10.287,18.923 12.557,16.653 R13.2@13.324,16.653 ; 10.345,21.648 S4.2@12.676,21.648 ; 10.287,34.373 cw(c11.728,34.373) 10.709,35.392 ccw(c11.728,34.373) 10.287,34.373 ; 10.287,34.373 ccw(c8.846,34.373) 9.865,35.392 cw(c8.846,34.373) 10.287,34.373 ; 11.205,21.648 cw(c11.205,20.177) 12.245,21.217 ccw(c11.205,20.177) 11.205,21.648 ; 11.205,21.648 ccw(c11.205,23.119) 12.245,22.079 cw(c11.205,23.119) 11.205,21.648 ; 12.577,16.653 cw(c12.577,15.906) 13.105,16.434 ccw(c12.577,15.906) 12.577,16.653 ; 12.577,16.653 ccw(c12.577,17.4) 13.105,16.872 cw(c12.577,17.4) 12.577,16.653
KEY-DOWN: P6.9 R7.2 S3.2 STC1.40 | length 60.5
  Top Layer w0.254: P6.9@17.907,35.814 20.086,37.993 STC1.40@20.086,46.954 ; 18.601,36.508 cw(c17.907,37.202) 17.907,36.22 ccw(c17.907,37.202) 18.601,36.508 ; 18.601,36.508 ccw(c19.295,35.814) 18.313,35.814 cw(c19.295,35.814) 18.601,36.508 ; 19.034,36.941 cw(c17.907,38.069) 17.907,36.474 ccw(c17.907,38.069) 19.034,36.941 ; 19.034,36.941 ccw(c20.162,35.814) 18.567,35.814 cw(c20.162,35.814) 19.034,36.941
  Top Layer w0.381: P6.9@17.907,35.814 20.574,33.147 23.876,33.147 25.527,31.496 25.527,18.796 23.384,16.653 R7.2@21.96,16.653 ; 25.585,21.648 S3.2@27.916,21.648 ; 18.926,34.795 cw(c19.945,35.814) 18.504,35.814 ccw(c19.945,35.814) 18.926,34.795 ; 18.926,34.795 ccw(c17.907,33.776) 17.907,35.217 cw(c17.907,33.776) 18.926,34.795 ; 22.707,16.653 cw(c22.707,17.4) 22.179,16.872 ccw(c22.707,17.4) 22.707,16.653 ; 22.707,16.653 ccw(c22.707,15.906) 22.179,16.434 cw(c22.707,15.906) 22.707,16.653 ; 26.445,21.648 cw(c26.445,20.177) 27.485,21.217 ccw(c26.445,20.177) 26.445,21.648 ; 26.445,21.648 ccw(c26.445,23.119) 27.485,22.079 cw(c26.445,23.119) 26.445,21.648
KEY-OK: P6.10 R6.2 S2.2 STC1.39 | length 56.7
  Top Layer w0.254: P6.10@15.367,35.814 19.586,40.033 STC1.39@19.586,46.954 ; 16.061,36.508 cw(c15.367,37.202) 15.367,36.22 ccw(c15.367,37.202) 16.061,36.508 ; 16.061,36.508 ccw(c16.755,35.814) 15.773,35.814 cw(c16.755,35.814) 16.061,36.508 ; 16.494,36.941 cw(c15.367,38.069) 15.367,36.474 ccw(c15.367,38.069) 16.494,36.941 ; 16.494,36.941 ccw(c17.622,35.814) 16.027,35.814 cw(c17.622,35.814) 16.494,36.941
  Top Layer w0.381: P6.10@15.367,35.814 20.32,30.861 20.32,18.669 19.166,17.515 R6.2@19.166,16.653 ; 20.32,21.59 20.378,21.648 S2.2@22.836,21.648 ; 16.386,34.795 cw(c17.405,35.814) 15.964,35.814 ccw(c17.405,35.814) 16.386,34.795 ; 16.386,34.795 ccw(c15.367,33.776) 15.367,35.217 cw(c15.367,33.776) 16.386,34.795 ; 19.166,17.45 cw(c18.419,17.45) 18.947,16.922 ccw(c18.419,17.45) 19.166,17.45 ; 19.166,17.45 ccw(c19.913,17.45) 19.385,16.922 cw(c19.913,17.45) 19.166,17.45 ; 21.365,21.648 cw(c21.365,20.177) 22.405,21.217 ccw(c21.365,20.177) 21.365,21.648 ; 21.365,21.648 ccw(c21.365,23.119) 22.405,22.079 cw(c21.365,23.119) 21.365,21.648
KEY-UP: P6.11 R5.1 S1.2 STC1.38 | length 56.3
  Top Layer w0.254: P6.11@12.827,35.814 19.086,42.073 STC1.38@19.086,46.954 ; 13.521,36.508 cw(c12.827,37.202) 12.827,36.22 ccw(c12.827,37.202) 13.521,36.508 ; 13.521,36.508 ccw(c14.215,35.814) 13.233,35.814 cw(c14.215,35.814) 13.521,36.508 ; 13.954,36.941 cw(c12.827,38.069) 12.827,36.474 ccw(c12.827,38.069) 13.954,36.941 ; 13.954,36.941 ccw(c15.082,35.814) 13.487,35.814 cw(c15.082,35.814) 13.954,36.941
  Top Layer w0.381: P6.11@12.827,35.814 12.827,34.544 ; 15.367,21.59 15.425,21.648 S1.2@17.756,21.648 ; R5.1@16.14,16.653 16.14,17.261 ; 12.827,34.544 cw(c13.879,34.544) 13.208,35.354 ccw(c13.879,34.544) 12.827,34.544 ; 12.827,34.544 ccw(c11.775,34.544) 12.446,35.354 cw(c11.775,34.544) 12.827,34.544 ; 12.827,34.544 15.367,32.004 15.367,18.034 16.14,17.261 ; 16.14,17.261 cw(c15.792,17.261) 15.976,16.966 ccw(c15.792,17.261) 16.14,17.261 ; 16.14,17.261 ccw(c16.488,17.261) 16.304,16.966 cw(c16.488,17.261) 16.14,17.261 ; 16.285,21.648 cw(c16.285,20.177) 17.325,21.217 ccw(c16.285,20.177) 16.285,21.648 ; 16.285,21.648 ccw(c16.285,23.119) 17.325,22.079 cw(c16.285,23.119) 16.285,21.648 ; 15.867,17.534 cw(c15.037,16.703) 16.212,16.703 ccw(c15.037,16.703) 15.867,17.534
LCD-CS: JLX1.12 P9.10 STC1.27 | length 65.6
  Top Layer w0.254: JLX1.12@9.652,81.661 9.652,77.343 0.889,68.58 0.889,64.008 3.048,61.849 P9.10@3.048,61.722 6.477,61.722 15.395,52.804 STC1.27@17.236,52.804 ; 4.029,61.722 cw(c4.029,62.703) 3.335,62.009 ccw(c4.029,62.703) 4.029,61.722 ; 4.029,61.722 ccw(c4.029,60.741) 3.335,61.435 cw(c4.029,60.741) 4.029,61.722 ; 4.642,61.722 cw(c4.642,63.316) 3.515,62.189 ccw(c4.642,63.316) 4.642,61.722 ; 4.642,61.722 ccw(c4.642,60.128) 3.515,61.255 cw(c4.642,60.128) 4.642,61.722 ; 9.652,80.067 cw(c11.246,80.067) 10.119,81.194 ccw(c11.246,80.067) 9.652,80.067 ; 9.652,80.067 ccw(c8.058,80.067) 9.185,81.194 cw(c8.058,80.067) 9.652,80.067 ; 9.652,80.68 cw(c10.633,80.68) 9.939,81.374 ccw(c10.633,80.68) 9.652,80.68 ; 9.652,80.68 ccw(c8.671,80.68) 9.365,81.374 cw(c8.671,80.68) 9.652,80.68 ; 1.831,63.066 cw(c0.487,61.722) 2.388,61.722 ccw(c0.487,61.722) 1.831,63.066 ; 2.137,62.76 ccw(c3.048,63.67) 3.048,62.382 cw(c3.048,63.67) 2.137,62.76 ; 2.264,62.633 cw(c1.354,61.722) 2.642,61.722 ccw(c1.354,61.722) 2.264,62.633
LCD-LED: P8.10 R11.1 STC1.22 | length 52.2
  Top Layer w0.254: P8.10@14.097,70.358 14.097,62.484 19.586,56.995 STC1.22@19.586,55.154 ; 14.097,68.764 cw(c15.691,68.764) 14.564,69.891 ccw(c15.691,68.764) 14.097,68.764 ; 14.097,68.764 ccw(c12.503,68.764) 13.63,69.891 cw(c12.503,68.764) 14.097,68.764 ; 14.097,69.377 cw(c15.078,69.377) 14.384,70.071 ccw(c15.078,69.377) 14.097,69.377 ; 14.097,69.377 ccw(c13.116,69.377) 13.81,70.071 cw(c13.116,69.377) 14.097,69.377
  Top Layer w0.381: P8.10@14.097,70.358 14.097,71.247 ; R11.1@21.828,74.56 17.41,74.56 14.097,71.247 ; 14.097,71.247 cw(c13.733,71.247) 13.871,70.91 ccw(c13.733,71.247) 14.097,71.247 ; 14.097,71.247 ccw(c14.461,71.247) 14.323,70.91 cw(c14.461,71.247) 14.097,71.247 ; 21.031,74.56 cw(c21.031,73.813) 21.559,74.341 ccw(c21.031,73.813) 21.031,74.56 ; 21.031,74.56 ccw(c21.031,75.307) 21.559,74.779 cw(c21.031,75.307) 21.031,74.56 ; P8.10@13.932,70.358 cw(c15.68,70.358) 14.444,71.594 ccw(c15.68,70.358) P8.10@13.932,70.358 ; P8.10@14.313,70.358 cw(c16.98,70.358) 15.094,72.244 ccw(c16.98,70.358) P8.10@14.313,70.358 ; P8.10@14.694,70.358 cw(c18.281,70.358) 15.745,72.895 ccw(c18.281,70.358) P8.10@14.694,70.358
LCD-REST: JLX1.11 P9.11 STC1.26 | length 64.7
  Top Layer w0.254: JLX1.11@12.192,81.661 12.192,78.613 1.397,67.818 1.397,65.405 2.54,64.262 4.826,64.262 15.784,53.304 STC1.26@17.236,53.304 ; 4.029,64.262 cw(c4.029,65.243) 3.335,64.549 ccw(c4.029,65.243) 4.029,64.262 ; 4.029,64.262 ccw(c4.029,63.281) 3.335,63.975 cw(c4.029,63.281) 4.029,64.262 ; 4.642,64.262 cw(c4.642,65.856) 3.515,64.729 ccw(c4.642,65.856) 4.642,64.262 ; 4.642,64.262 ccw(c4.642,62.668) 3.515,63.795 cw(c4.642,62.668) 4.642,64.262 ; 12.192,80.067 cw(c13.786,80.067) 12.659,81.194 ccw(c13.786,80.067) 12.192,80.067 ; 12.192,80.067 ccw(c10.598,80.067) 11.725,81.194 cw(c10.598,80.067) 12.192,80.067 ; 12.192,80.68 cw(c13.173,80.68) 12.479,81.374 ccw(c13.173,80.68) 12.192,80.68 ; 12.192,80.68 ccw(c11.211,80.68) 11.905,81.374 cw(c11.211,80.68) 12.192,80.68 ; 1.651,65.151 ccw(c2.451,65.95) 2.828,64.885 cw(c2.451,65.95) 1.651,65.151 ; 1.936,64.866 ccw(c2.599,65.53) 2.912,64.645 cw(c2.599,65.53) 1.936,64.866 ; 2.22,64.582 ccw(c2.748,65.109) 2.997,64.406 cw(c2.748,65.109) 2.22,64.582 ; 2.28,64.522 cw(c2.02,64.262) 2.388,64.262 ccw(c2.02,64.262) 2.28,64.522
